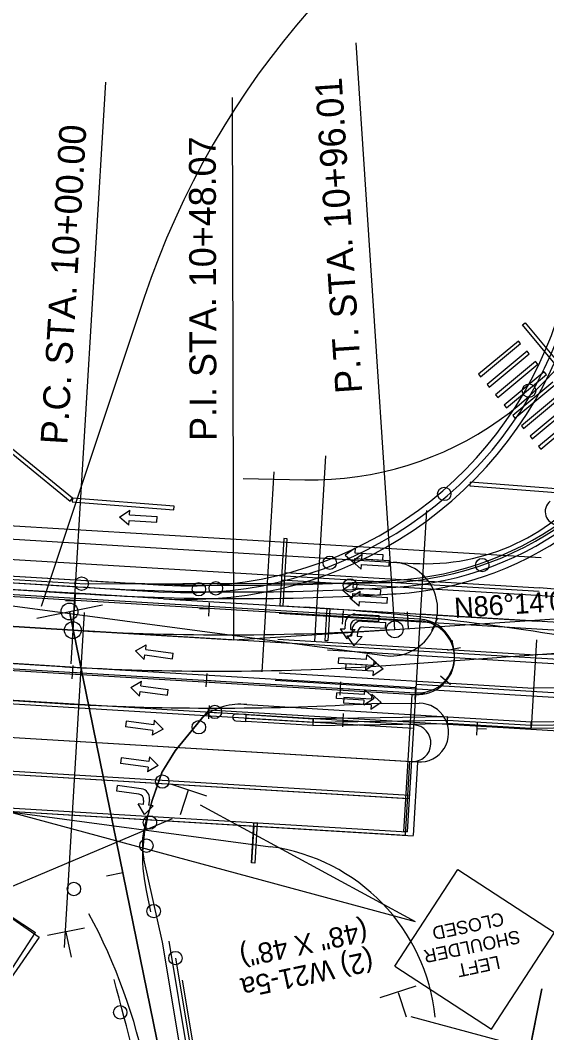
# Model space of a CAD drawing. Extents: x 659657 to 668193, y 633084 to 648639.
# Drawn here: x 661664 to 661820.9, y 642355.9 to 642657.6 of the extents above; entities that cross this region are included whole.
import ezdxf

# ---------------------------------------------------------------- set-up
doc = ezdxf.new("R2010")
doc.units = 0
for name, color, linetype in [('R_Border PE', 7, 'Continuous'), ('R_Draft', 7, 'Continuous'), ('R_MOT_Stage 1', 7, 'Continuous'), ('R_MOT_Stage 1_Striping', 7, 'Continuous'), ('R_MOT_Stage 2', 7, 'Continuous'), ('R_MOT_Stage 2_Striping', 7, 'Continuous'), ('R_MOT_Stage 3', 7, 'Continuous'), ('R_MOT_STAGE 3_ALG', 7, 'Continuous'), ('R_MOT_Stage 3_Striping', 7, 'Continuous'), ('R_MOT_Stage 4', 7, 'Continuous'), ('R_MOT_Stage 4_Striping', 7, 'Continuous'), ('R_MOT_Stage 4_Striping_PPM', 7, 'Continuous'), ('R_MOT_Stage 5', 7, 'Continuous'), ('R_MOT_Stage 5_Striping', 7, 'Continuous'), ('R_MOT_Stage 5_Striping_PPM', 7, 'Continuous'), ('S_EXISTING_ALIGNMENT', 7, 'Continuous'), ('T_Notes', 7, 'Continuous'), ('T_SIGNAL CONTROL CABINET', 7, 'Continuous')]:
    doc.layers.add(name, color=color, linetype=linetype)

msp = doc.modelspace()

# ---------------------------------------------------------------- linework, layer by layer
at = {"layer": 'R_Border PE'}
for p, q in [((661708.77, 642430.02), (661719.46, 642426.49)), ((661714.04, 642428.11), (661711.63, 642420.82)), ((661652.97, 642395.9), (661709.36, 642419.75)), ((661639.72, 642404.5), (661668.55, 642385.78)), ((661649.81, 642356.94), (661668.55, 642385.78))]:
    msp.add_line(p, q, dxfattribs=at)
at = {"layer": 'R_Draft'}
for p, q in [((661781.76, 642388.96), (661612.73, 642434.51)), ((661708.77, 642430.02), (661719.46, 642426.49)), ((661714.04, 642428.11), (661711.63, 642420.82)), ((661781.76, 642388.96), (661717.68, 642423.66)), ((661641.34, 642403.95), (661669.62, 642384.39)), ((661775.62, 642375.69), (661794.37, 642404.5)), ((661794.37, 642404.5), (661823.2, 642385.78)), ((661672.07, 642384.9), (661683.09, 642387.16)), ((661669.62, 642384.39), (661650.07, 642356.12)), ((661677.58, 642385.86), (661679.13, 642378.34)), ((661804.46, 642356.94), (661823.2, 642385.78)), ((661775.62, 642375.69), (661804.46, 642356.94))]:
    msp.add_line(p, q, dxfattribs=at)
at = {"layer": 'R_MOT_Stage 1'}
for p, q in [((661720.18, 642449.39), (661720.42, 642453.36)), ((661720.36, 642451.36), (661723.07, 642451.2)), ((661760.11, 642446.98), (661760.35, 642450.95)), ((661760.28, 642448.95), (661763, 642448.79)), ((661800.03, 642444.57), (661800.27, 642448.54)), ((661800.21, 642446.54), (661802.92, 642446.38))]:
    msp.add_line(p, q, dxfattribs=at)
for centre in [(661717.2, 642446.89), (661706.31, 642430.71), (661701.59, 642411.6), (661703.75, 642392.11)]:
    msp.add_circle(centre, 2, dxfattribs=at)
at = {"layer": 'R_MOT_Stage 1_Striping'}
for p, q in [((661741.75, 642490.84), (661883.49, 642482.29)), ((661717.22, 642292.66), (661678.66, 642481.38)), ((661741.15, 642480.86), (661840.96, 642474.84)), ((661755.52, 642469.98), (661882.28, 642462.32)), ((661739.94, 642460.9), (661881.68, 642452.34)), ((661720.18, 642452.07), (661866.25, 642443.26))]:
    msp.add_line(p, q, dxfattribs=at)
for points in [[(661668.87, 642479.38), (661688.46, 642483.38)], [(661720.18, 642452.07), (661710.1, 642439.86), (661706.26, 642433.6)], [(661706.26, 642433.6), (661703.29, 642425.07), (661702.78, 642423.26), (661701.93, 642420.3), (661701.36, 642417.3), (661701.05, 642416.03), (661700.7, 642412.89), (661700.42, 642409.79), (661700.42, 642406.63), (661700.53, 642404.85), (661700.94, 642401.79), (661701.36, 642398.75), (661702.77, 642391.91)], [(661689.65, 642402.62), (661694.55, 642403.62)]]:
    msp.add_lwpolyline(points, dxfattribs=at)
msp.add_circle((661678.66, 642481.38), 2.5, dxfattribs=at)
msp.add_arc((661531.76, 642309.13), 173.41, 11.5425, 28.301, dxfattribs=at)
at = {"layer": 'R_MOT_Stage 2'}
for p, q in [((661731.31, 642450.65), (661728.31, 642450.83)), ((661728.19, 642448.84), (661731.19, 642448.65)), ((661724.83, 642284.52), (661708.38, 642383.18)), ((661726.81, 642284.81), (661712.34, 642371.58))]:
    msp.add_line(p, q, dxfattribs=at)
for points in [[(661751.15, 642447.45), (661731.19, 642448.65), (661731.31, 642450.65), (661751.27, 642449.45)], [(661751.2, 642449.44), (661751.22, 642447.44), (661791.34, 642448.03), (661791.31, 642450.03)], [(661791.38, 642450.03), (661816.33, 642448.52), (661816.21, 642446.53), (661791.26, 642448.03)], [(661816.26, 642448.52), (661896.47, 642449.69), (661896.5, 642447.69), (661816.29, 642446.53)]]:
    msp.add_lwpolyline(points, close=True, dxfattribs=at)
for centre in [(661721.97, 642451.48), (661702.61, 642418.51), (661679.95, 642398.71), (661710.24, 642378.12), (661693.77, 642361.94)]:
    msp.add_circle(centre, 2, dxfattribs=at)
msp.add_arc((661728.25, 642449.83), 1, 86.5452, 266.5452, dxfattribs=at)
at = {"layer": 'R_MOT_Stage 2_Striping'}
for p, q in [((661742.92, 642493.03), (661818.74, 642488.45)), ((661898.48, 642481.63), (661818.74, 642488.45)), ((661717.22, 642292.66), (661678.66, 642481.38)), ((661742.32, 642483.05), (661818.14, 642478.47)), ((661740.72, 642473.12), (661817.54, 642468.49)), ((661897.81, 642470.65), (661817.54, 642468.49)), ((661741.11, 642463.08), (661816.94, 642458.5)), ((661897.15, 642459.67), (661816.94, 642458.5)), ((661731.49, 642453.65), (661791.38, 642450.03)), ((661710.1, 642439.86), (661718.32, 642449.82)), ((661706.19, 642433.39), (661710.1, 642439.86)), ((661706.36, 642382.86), (661700.84, 642407.68)), ((661722.85, 642284.23), (661706.36, 642382.86))]:
    msp.add_line(p, q, dxfattribs=at)
for points in [[(661679.5, 642515.11), (661651.86, 642537.73), (661651.17, 642536.89), (661678.82, 642514.27)], [(661709.88, 642512.74), (661679.5, 642515.11), (661679.42, 642514.05), (661709.8, 642511.69)], [(661742.53, 642503.12), (661741.32, 642483.11), (661742.32, 642483.05), (661743.53, 642503.06)], [(661755.32, 642482.26), (661754.75, 642472.78), (661755.75, 642472.72), (661756.32, 642482.2)]]:
    msp.add_lwpolyline(points, close=True, dxfattribs=at)
for points in [[(661668.87, 642479.38), (661688.46, 642483.38)], [(661701.14, 642417.52), (661702.78, 642423.26), (661703.29, 642425.07), (661706.19, 642433.39)], [(661689.65, 642402.62), (661694.55, 642403.62)]]:
    msp.add_lwpolyline(points, dxfattribs=at)
msp.add_circle((661678.66, 642481.38), 2.5, dxfattribs=at)
for centre, radius, start, end in [((661729.57, 642435.68), 18.07, 83.9065, 128.4951), ((661720.37, 642412.02), 20, 164.0371, 192.5265), ((660710.1, 642104.2), 1017.63, 10.09916, 15.23969)]:
    msp.add_arc(centre, radius, start, end, dxfattribs=at)
at = {"layer": 'R_MOT_Stage 3'}
for p, q in [((661583.81, 642496.62), (661680.56, 642490.78)), ((661583.69, 642494.63), (661680.44, 642488.79)), ((661774.68, 642490.61), (661775.81, 642490.68)), ((661774.8, 642488.61), (661775.93, 642488.68))]:
    msp.add_line(p, q, dxfattribs=at)
for centre in [(661801.68, 642495.21), (661682.27, 642489.68), (661722.27, 642488.29), (661762.27, 642489.15)]:
    msp.add_circle(centre, 2, dxfattribs=at)
for centre, radius, start, end in [((661769.94, 642586.5), 96, 273.5027, 341.5452), ((661769.94, 642586.5), 98, 273.5027, 341.5452), ((661728.98, 643236.54), 747.33, 266.28685, 273.50587), ((661774.93, 642486.62), 4, 93.5027, 93.5059), ((661728.98, 643236.54), 749.33, 266.28685, 273.50587), ((661774.93, 642486.62), 2, 93.5027, 93.5059)]:
    msp.add_arc(centre, radius, start, end, dxfattribs=at)
at = {"layer": 'R_MOT_STAGE 3_ALG'}
for p, q in [((661775.61, 642476.07), (661857.55, 642481.46)), ((661679.66, 642475.81), (661727.64, 642472.91)), ((661727.64, 642472.91), (661775.61, 642476.07))]:
    msp.add_line(p, q, dxfattribs=at)
for points in [[(661775.61, 642476.07), (661764.11, 642650.79)], [(661679.66, 642475.81), (661689.52, 642639.09)], [(661727.64, 642472.91), (661727.21, 642634.55)], [(661680.26, 642485.79), (661679.06, 642465.83)], [(661779.26, 642481.32), (661779.59, 642476.33)]]:
    msp.add_lwpolyline(points, dxfattribs=at)
for centre in [(661679.66, 642475.81), (661775.61, 642476.07)]:
    msp.add_circle(centre, 2.5, dxfattribs=at)
msp.add_arc((661725.58, 643236.42), 762, 266.54523, 273.76425, dxfattribs=at)
at = {"layer": 'R_MOT_Stage 3_Striping'}
for p, q in [((661583.57, 642492.63), (661680.32, 642486.79)), ((661774.93, 642486.62), (661776.05, 642486.69)), ((661582.91, 642481.65), (661679.66, 642475.81)), ((661775.61, 642476.07), (661857.55, 642481.46)), ((661582.24, 642470.67), (661676.49, 642464.98)), ((661777.42, 642465.58), (661855.87, 642471.26)), ((661579.92, 642459.79), (661675.83, 642454)), ((661768.65, 642453.98), (661782.89, 642454.03)), ((661579.43, 642448.8), (661782.39, 642436.55)), ((661580.25, 642437.73), (661779.89, 642425.68)), ((661782.39, 642436.52), (661781.07, 642414.69)), ((661579.59, 642426.75), (661781.07, 642414.59)), ((661733.58, 642417.45), (661732.93, 642406.58)), ((661819.42, 642368.99), (661768.65, 642114.24))]:
    msp.add_line(p, q, dxfattribs=at)
for centre, radius, start, end in [((661769.94, 642586.5), 100, 273.5027, 341.5452), ((661728.98, 643236.54), 751.33, 266.28685, 273.50587), ((661725.58, 643236.42), 762, 266.54523, 273.76425), ((661722.41, 643225.59), 762, 266.99169, 274.13987), ((661722.41, 643225.59), 762, 266.54523, 266.99169), ((661722.41, 643225.59), 773, 266.54523, 266.99169), ((661722.41, 643225.59), 773, 266.99169, 273.42942), ((661782.92, 642445.28), 8.75, 266.5452, 90.2072)]:
    msp.add_arc(centre, radius, start, end, dxfattribs=at)
at = {"layer": 'R_MOT_Stage 4'}
for p, q in [((661583.81, 642496.62), (661706.92, 642489.19)), ((661583.69, 642494.63), (661706.8, 642487.19))]:
    msp.add_line(p, q, dxfattribs=at)
for centre in [(661815.63, 642547.17), (661790.36, 642516.41), (661756.24, 642495.91), (661682.27, 642489.68), (661717.23, 642488.03)]:
    msp.add_circle(centre, 2, dxfattribs=at)
for radius in [116, 118]:
    msp.add_arc((661713.91, 642604.98), radius, 266.5452, 341.5452, dxfattribs=at)
at = {"layer": 'R_MOT_Stage 4_Striping'}
for p, q in [((661683.39, 642486.6), (661583.57, 642492.63)), ((661706.68, 642485.2), (661683.39, 642486.6)), ((661706.68, 642485.2), (661790.16, 642480.16)), ((661679.66, 642475.81), (661582.91, 642481.65)), ((661839.66, 642477.17), (661783.2, 642480.58)), ((661782.54, 642469.6), (661679.66, 642475.81)), ((661682.06, 642464.64), (661582.24, 642470.67)), ((661842.49, 642465.98), (661782.54, 642469.6)), ((661781.88, 642458.62), (661682.06, 642464.64)), ((661781.22, 642447.64), (661587.07, 642459.36)), ((661840.81, 642456.06), (661781.94, 642459.62)), ((661586.41, 642448.38), (661780.55, 642436.66)), ((661580.25, 642437.73), (661779.47, 642425.7)), ((661778.81, 642414.72), (661780.14, 642436.68)), ((661579.59, 642426.75), (661778.81, 642414.72)), ((661732.92, 642406.47), (661733.58, 642417.45))]:
    msp.add_line(p, q, dxfattribs=at)
msp.add_lwpolyline([(661845.56, 642516.22), (661798.06, 642519.91), (661797.98, 642518.86), (661845.48, 642515.17)], close=True, dxfattribs=at)
for centre, radius, end in [((661713.91, 642604.98), 120, 341.5452), ((661780.89, 642442.15), 5.5, 86.5452)]:
    msp.add_arc(centre, radius, 266.5452, end, dxfattribs=at)
at = {"layer": 'R_MOT_Stage 4_Striping_PPM'}
msp.add_lwpolyline([(661665.6, 641597.22), (661725.66, 641898.57), (661819.42, 642368.96)], dxfattribs=at)
msp.add_arc((660777.38, 642087.58), 954.93, 348.72774, 348.72774, dxfattribs=at)
at = {"layer": 'R_MOT_Stage 5'}
for p, q in [((661680.17, 642484.44), (661677.46, 642484.6)), ((661680.35, 642486.41), (661680.11, 642482.44)), ((661720.28, 642484), (661720.04, 642480.03)), ((661720.1, 642482.03), (661717.39, 642482.19)), ((661760.2, 642481.59), (661759.96, 642477.62)), ((661760.03, 642479.61), (661757.32, 642479.78)), ((661787.39, 642477.52), (661784.97, 642478.77)), ((661788.34, 642479.26), (661786.52, 642475.72)), ((661793.26, 642470.21), (661792.75, 642472.87)), ((661795.21, 642470.52), (661791.3, 642469.78)), ((661679.48, 642461.31), (661679.72, 642465.28)), ((661679.66, 642463.29), (661682.37, 642463.12)), ((661719.41, 642458.9), (661719.65, 642462.87)), ((661790.75, 642460.87), (661792.55, 642462.91)), ((661719.59, 642460.88), (661722.3, 642460.71)), ((661759.34, 642456.49), (661759.58, 642460.46)), ((661792.2, 642459.52), (661789.21, 642462.15)), ((661759.52, 642458.46), (661762.23, 642458.3)), ((661781.67, 642455.13), (661781.91, 642459.11)), ((661781.85, 642457.11), (661784.56, 642456.94))]:
    msp.add_line(p, q, dxfattribs=at)
at = {"layer": 'R_MOT_Stage 5_Striping'}
for p, q in [((661239.9, 642532.41), (661819.29, 642497.43)), ((661239.3, 642522.43), (661818.68, 642487.45)), ((661237.31, 642489.49), (661781.76, 642456.62)), ((661633.25, 642487.63), (661783.08, 642478.58)), ((661236.71, 642479.51), (661781.16, 642446.64)), ((661236.1, 642469.53), (661780.55, 642436.66)), ((661235.5, 642459.54), (661779.95, 642426.68)), ((661579.65, 642427.75), (661779.29, 642415.7))]:
    msp.add_line(p, q, dxfattribs=at)
for points in [[(661781.76, 642456.62), (661779.29, 642415.7), (661778.29, 642415.76), (661780.76, 642456.68)], [(661734.6, 642418.39), (661733.92, 642406.41), (661732.92, 642406.47), (661733.6, 642418.45)]]:
    msp.add_lwpolyline(points, close=True, dxfattribs=at)
msp.add_arc((661782.42, 642467.6), 11, 266.5452, 86.5452, dxfattribs=at)
at = {"layer": 'R_MOT_Stage 5_Striping_PPM'}
for p, q in [((661812.47, 642561.98), (661800.56, 642552.06)), ((661813.11, 642561.21), (661812.47, 642561.98)), ((661801.2, 642551.3), (661813.11, 642561.21)), ((661815.03, 642558.91), (661803.12, 642548.99)), ((661815.67, 642558.14), (661815.03, 642558.91)), ((661803.76, 642548.22), (661815.67, 642558.14)), ((661817.59, 642555.83), (661805.68, 642545.92)), ((661818.23, 642555.07), (661817.59, 642555.83)), ((661806.32, 642545.15), (661818.23, 642555.07)), ((661800.56, 642552.06), (661801.2, 642551.3)), ((661820.15, 642552.76), (661808.24, 642542.84)), ((661808.88, 642542.07), (661820.79, 642551.99)), ((661820.79, 642551.99), (661820.15, 642552.76)), ((661803.12, 642548.99), (661803.76, 642548.22)), ((661822.71, 642549.69), (661810.8, 642539.77)), ((661811.44, 642539), (661823.35, 642548.92)), ((661805.68, 642545.92), (661806.32, 642545.15)), ((661825.27, 642546.61), (661813.36, 642536.69)), ((661814, 642535.93), (661825.91, 642545.84)), ((661808.24, 642542.84), (661808.88, 642542.07)), ((661827.83, 642543.54), (661815.92, 642533.62)), ((661816.56, 642532.85), (661828.47, 642542.77)), ((661810.8, 642539.77), (661811.44, 642539)), ((661830.39, 642540.47), (661818.48, 642530.55)), ((661819.12, 642529.78), (661831.03, 642539.7)), ((661813.36, 642536.69), (661814, 642535.93)), ((661815.92, 642533.62), (661816.56, 642532.85)), ((661818.48, 642530.55), (661819.12, 642529.78))]:
    msp.add_line(p, q, dxfattribs=at)
msp.add_lwpolyline([(661814.44, 642567.43), (661842.3, 642533.98), (661841.53, 642533.34), (661813.67, 642566.79)], close=True, dxfattribs=at)
msp.add_lwpolyline([(661665.6, 641597.22), (661725.66, 641898.57), (661819.42, 642368.96)], dxfattribs=at)
for centre, radius, start, end in [((660777.38, 642087.58), 954.93, 348.72774, 348.72774), ((661824.44, 642511.15), 4, 128.8878, 266.5452)]:
    msp.add_arc(centre, radius, start, end, dxfattribs=at)
at = {"layer": 'S_EXISTING_ALIGNMENT'}
for p, q in [((661700.95, 642574.97), (661670.21, 642482.86)), ((661678.66, 642481.38), (661717.22, 642292.66))]:
    msp.add_line(p, q, dxfattribs=at)
msp.add_arc((661937.25, 642496.11), 249.11, 115.6664, 161.5452, dxfattribs=at)
at = {"layer": 'T_Notes'}
for p, q in [((661781.89, 642369.77), (661771.2, 642366.24)), ((661776.62, 642367.86), (661779.03, 642360.57)), ((661899.09, 642328.71), (661780.53, 642360.66))]:
    msp.add_line(p, q, dxfattribs=at)
at = {"layer": 'T_SIGNAL CONTROL CABINET'}
for p, q in [((661730.38, 642521.03), (661748.84, 642520.66)), ((661392.07, 642519.22), (661772.52, 642468.24)), ((661392.07, 642519.22), (661781.09, 642495.73)), ((661693.56, 642509.53), (661696.61, 642511.6)), ((661696.53, 642510.2), (661696.61, 642511.6)), ((661785.07, 642511.52), (661781.26, 642448.44)), ((661696.34, 642507.11), (661693.56, 642509.53)), ((661696.34, 642507.11), (661696.43, 642508.51)), ((661696.43, 642508.51), (661704.69, 642508.02)), ((661696.53, 642510.2), (661704.79, 642509.7)), ((661704.69, 642508.02), (661704.79, 642509.7)), ((661763.84, 642500.28), (661760.79, 642498.21)), ((661763.84, 642500.28), (661763.75, 642498.88)), ((661763.75, 642498.88), (661772.01, 642498.38)), ((661562.49, 642496.91), (661683.47, 642489.6)), ((661760.79, 642498.21), (661763.57, 642495.79)), ((661762.86, 642496.38), (661765.91, 642498.45)), ((661765.64, 642493.96), (661762.86, 642496.38)), ((661763.65, 642497.19), (661763.57, 642495.79)), ((661763.65, 642497.19), (661771.91, 642496.69)), ((661765.82, 642497.05), (661765.91, 642498.45)), ((661765.82, 642497.05), (661774.08, 642496.55)), ((661772.01, 642498.38), (661771.91, 642496.69)), ((661773.98, 642494.87), (661774.08, 642496.55)), ((661765.64, 642493.96), (661765.72, 642495.36)), ((661765.72, 642495.36), (661773.98, 642494.87)), ((661237.34, 642489.99), (661781.79, 642457.12)), ((661783.11, 642479.08), (661573.4, 642491.74)), ((661683.47, 642489.6), (661770.43, 642489.92)), ((661763.2, 642489.8), (661760.15, 642487.73)), ((661763.2, 642489.8), (661763.12, 642488.4)), ((661760.15, 642487.73), (661762.93, 642485.31)), ((661762.19, 642485.4), (661765.25, 642487.47)), ((661763.02, 642486.71), (661762.93, 642485.31)), ((661763.02, 642486.71), (661771.28, 642486.21)), ((661763.12, 642488.4), (661771.38, 642487.9)), ((661765.16, 642486.07), (661765.25, 642487.47)), ((661771.38, 642487.9), (661771.28, 642486.21)), ((661764.97, 642482.98), (661762.19, 642485.4)), ((661764.97, 642482.98), (661765.06, 642484.38)), ((661765.06, 642484.38), (661773.32, 642483.89)), ((661765.16, 642486.07), (661773.42, 642485.57)), ((661773.32, 642483.89), (661773.42, 642485.57)), ((661683.05, 642481.11), (661677.03, 642381.3)), ((661763.77, 642480.59), (661770.91, 642480.16)), ((661760.8, 642477.95), (661760.69, 642476.18)), ((661764.23, 642478.87), (661770.81, 642478.48)), ((661765.83, 642478.51), (661772.97, 642478.08)), ((661770.81, 642478.48), (661770.91, 642480.16)), ((661772.87, 642476.4), (661772.97, 642478.08)), ((661759.29, 642476.26), (661761.36, 642473.21)), ((661759.29, 642476.26), (661760.69, 642476.18)), ((661761.36, 642473.21), (661763.78, 642475.99)), ((661762.45, 642477.29), (661762.38, 642476.07)), ((661762.38, 642476.07), (661763.78, 642475.99)), ((661762.86, 642475.88), (661762.75, 642474.1)), ((661764.51, 642475.21), (661764.43, 642474)), ((661766.29, 642476.8), (661772.87, 642476.4)), ((661698.36, 642469.66), (661701.55, 642471.5)), ((661701.36, 642470.11), (661701.55, 642471.5)), ((661761.34, 642474.18), (661763.41, 642471.13)), ((661761.34, 642474.18), (661762.75, 642474.1)), ((661763.41, 642471.13), (661765.84, 642473.91)), ((661764.43, 642474), (661765.84, 642473.91)), ((661817.81, 642472.98), (661816.22, 642446.58)), ((661700.95, 642467.04), (661698.36, 642469.66)), ((661700.95, 642467.04), (661701.14, 642468.43)), ((661701.14, 642468.43), (661709.34, 642467.33)), ((661701.36, 642470.11), (661709.56, 642469.01)), ((661709.34, 642467.33), (661709.56, 642469.01)), ((661767.2, 642467.11), (661767.28, 642468.52)), ((661770.06, 642466.09), (661767.28, 642468.52)), ((661758.84, 642465.93), (661758.94, 642467.61)), ((661767.1, 642465.43), (661758.84, 642465.93)), ((661767.2, 642467.11), (661758.94, 642467.61)), ((661761.01, 642465.78), (661760.91, 642464.1)), ((661769.27, 642465.28), (661761.01, 642465.78)), ((661767.01, 642464.02), (661770.06, 642466.09)), ((661767.01, 642464.02), (661767.1, 642465.43)), ((661769.36, 642466.69), (661769.27, 642465.28)), ((661769.36, 642466.69), (661772.14, 642464.27)), ((661769.17, 642463.6), (661760.91, 642464.1)), ((661772.14, 642464.27), (661769.08, 642462.2)), ((661769.17, 642463.6), (661769.08, 642462.2)), ((661696.89, 642458.76), (661700.09, 642460.6)), ((661699.9, 642459.2), (661700.09, 642460.6)), ((661699.49, 642456.14), (661696.89, 642458.76)), ((661699.49, 642456.14), (661699.68, 642457.53)), ((661699.68, 642457.53), (661707.88, 642456.43)), ((661699.9, 642459.2), (661708.1, 642458.1)), ((661707.88, 642456.43), (661708.1, 642458.1)), ((661758.2, 642455.44), (661758.31, 642457.13)), ((661766.57, 642456.63), (661758.31, 642457.13)), ((661766.57, 642456.63), (661766.65, 642458.03)), ((661769.43, 642455.61), (661766.65, 642458.03)), ((661768.75, 642456.71), (661768.67, 642455.3)), ((661768.75, 642456.71), (661771.53, 642454.28)), ((661766.46, 642454.95), (661758.2, 642455.44)), ((661760.41, 642455.8), (661760.31, 642454.12)), ((661768.57, 642453.62), (661760.31, 642454.12)), ((661768.67, 642455.3), (661760.41, 642455.8)), ((661766.38, 642453.54), (661769.43, 642455.61)), ((661766.38, 642453.54), (661766.46, 642454.95)), ((661771.53, 642454.28), (661768.48, 642452.21)), ((661768.57, 642453.62), (661768.48, 642452.21)), ((661695.55, 642448.69), (661695.32, 642447.02)), ((661703.75, 642447.59), (661695.55, 642448.69)), ((661703.93, 642448.98), (661703.75, 642447.59)), ((661703.93, 642448.98), (661706.53, 642446.37)), ((661731.25, 642449.65), (661751.21, 642448.45)), ((661751.21, 642448.45), (661791.32, 642449.03)), ((661703.52, 642445.92), (661695.32, 642447.02)), ((661706.53, 642446.37), (661703.34, 642444.52)), ((661703.52, 642445.92), (661703.34, 642444.52)), ((661550.24, 642436.54), (661738.52, 642411.31)), ((661694.08, 642437.79), (661693.86, 642436.11)), ((661702.06, 642435.01), (661693.86, 642436.11)), ((661702.29, 642436.69), (661694.08, 642437.79)), ((661705.07, 642435.46), (661701.88, 642433.62)), ((661702.47, 642438.08), (661702.29, 642436.69)), ((661702.47, 642438.08), (661705.07, 642435.46)), ((661702.06, 642435.01), (661701.88, 642433.62)), ((661692.75, 642427.84), (661692.98, 642429.52)), ((661700.06, 642428.57), (661692.98, 642429.52)), ((661699.28, 642426.97), (661692.75, 642427.84)), ((661701.02, 642420.86), (661699.17, 642424.05)), ((661700.57, 642423.86), (661699.17, 642424.05)), ((661700.73, 642425.07), (661700.57, 642423.86)), ((661703.63, 642423.45), (661701.02, 642420.86)), ((661702.48, 642425.41), (661702.24, 642423.64)), ((661703.63, 642423.45), (661702.24, 642423.64)), ((661710.24, 642378.12), (661725.82, 642284.66))]:
    msp.add_line(p, q, dxfattribs=at)
for points in [[(661754.99, 642527.72), (661751.66, 642472.46)], [(661736.08, 642463.39), (661739.68, 642523.03)], [(661791.32, 642449.03), (661816.27, 642447.52), (661896.49, 642448.69), (662330.7, 642422.48), (662410.19, 642411.67)]]:
    msp.add_lwpolyline(points, dxfattribs=at)
for centre, radius, start, end in [((661750.82, 642617.63), 97, 268.8358, 341.5452), ((661770.08, 642586.92), 97, 270.2072, 341.5452), ((661784.89, 642558.62), 63, 266.5452, 323.7924), ((661774.38, 642482.11), 14, 262.3676, 86.5452), ((661703.06, 641722.03), 762, 79.70245, 86.54523), ((661763.61, 642477.78), 2.81, 86.5452, 176.5452), ((661764.13, 642477.19), 1.69, 86.5452, 176.5452), ((661765.66, 642475.71), 2.81, 86.5452, 176.5452), ((661782.45, 642468.1), 11, 266.545, 86.5454), ((661766.19, 642475.11), 1.69, 86.5452, 176.5452), ((661699.06, 642425.3), 1.69, 352.3676, 82.3676), ((661699.69, 642425.78), 2.81, 352.3676, 82.3676), ((661730.94, 642354.81), 57, 5.7842, 82.3676)]:
    msp.add_arc(centre, radius, start, end, dxfattribs=at)

# ---------------------------------------------------------------- texts
at = {"layer": 'R_Draft'}
for s, height, rotation, p in [('(48" X 48")', 6, 191.9786, (661766.84, 642389.16)), ('CLOSED', 3.94, 191.9772, (661807.67, 642391.8)), ('SHOULDER', 3.94, 191.9772, (661812.53, 642386.49)), ('(2) W21-5a', 6, 191.9786, (661768.54, 642380.32)), ('LEFT', 3.94, 191.9776, (661806.51, 642378.88))]:
    msp.add_text(s, height=height, rotation=rotation, dxfattribs=at).set_placement(p)
at = {"layer": 'R_MOT_STAGE 3_ALG'}
for s, height, rotation, p in [('P.T. STA. 10+96.01', 8, 93.7642, (661765.95, 642546.61)), ('P.C. STA. 10+00.00', 8, 86.5452, (661677.98, 642530.95)), ('P.I. STA. 10+48.07', 8, 90.1547, (661722.48, 642532.24)), ('N86%%d14\'09"E', 6, 3.7642, (661793.53, 642479.44))]:
    msp.add_text(s, height=height, rotation=rotation, dxfattribs=at).set_placement(p)

doc.saveas('drawing.dxf')
